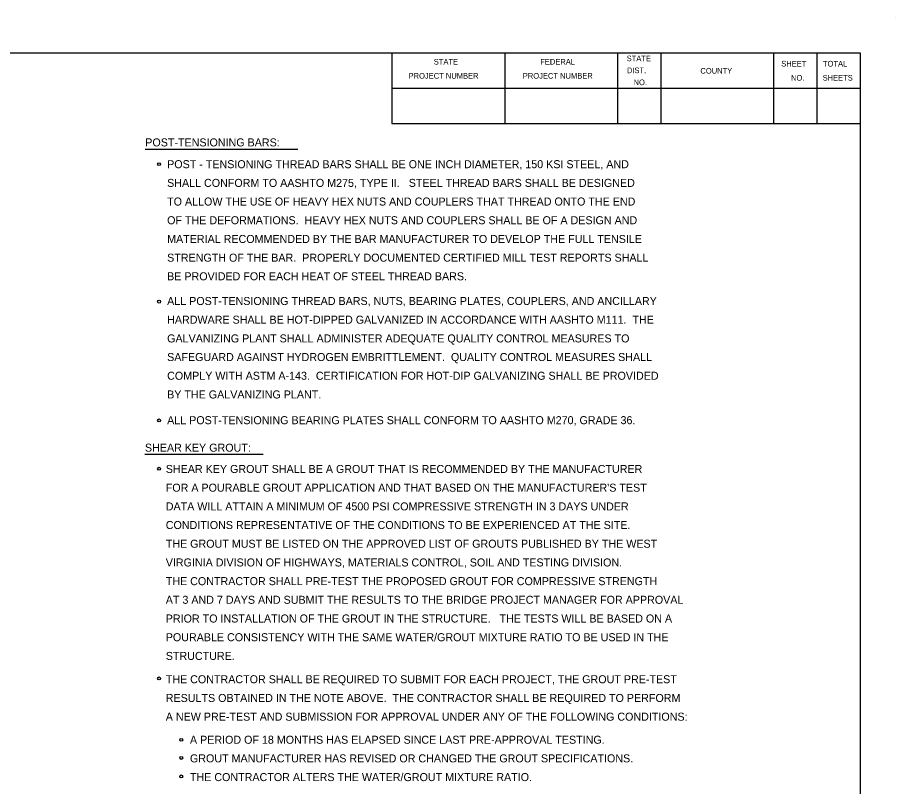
# Model space of a CAD drawing. Extents: x 762.3 to 790.4, y -1231.3 to -1213.2.
# Drawn here: x 780.09 to 790.37, y -1222.18 to -1213.19 of the extents above; entities that cross this region are included whole.
import ezdxf

# ---------------------------------------------------------------- set-up
doc = ezdxf.new("R2010")
doc.units = 0
doc.layers.add('Default', color=7, linetype='Continuous')

msp = doc.modelspace()

# ---------------------------------------------------------------- linework, layer by layer
at = {"layer": 'Default'}
for p, q in [((790.367, -1213.186), (790.367, -1213.186)), ((763.554, -1213.599), (789.954, -1213.599)), ((784.472, -1213.599), (784.472, -1214.424)), ((785.293, -1213.599), (785.293, -1213.599)), ((785.792, -1213.599), (785.792, -1214.424)), ((787.112, -1213.599), (787.112, -1214.424)), ((787.619, -1213.599), (787.619, -1214.424)), ((788.939, -1213.599), (788.939, -1214.424)), ((789.447, -1213.599), (789.447, -1214.424)), ((789.954, -1213.599), (789.954, -1230.924)), ((789.954, -1213.599), (789.954, -1213.599)), ((789.954, -1213.599), (789.954, -1213.599)), ((784.472, -1214.011), (789.954, -1214.011)), ((784.472, -1214.424), (789.954, -1214.424)), ((781.582, -1214.726), (783.369, -1214.726)), ((781.58, -1218.295), (782.963, -1218.295))]:
    msp.add_line(p, q, dxfattribs=at)
for centre in [(781.746, -1214.902), (781.746, -1216.511), (781.746, -1217.901), (781.746, -1218.467), (781.746, -1220.92), (782.005, -1221.639), (782.005, -1221.851), (782.005, -1222.067)]:
    msp.add_circle(centre, 0.0172, dxfattribs=at)

# ---------------------------------------------------------------- texts
for s, height, p in [('STATE', 0.066, (784.962, -1213.736)), ('FEDERAL ', 0.066, (786.208, -1213.736)), ('STATE', 0.066, (787.22, -1213.697)), ('SHEET ', 0.066, (789.03, -1213.759)), ('TOTAL ', 0.066, (789.518, -1213.759)), ('DIST. ', 0.066, (787.223, -1213.837)), ('COUNTY', 0.066, (788.083, -1213.842)), ('PROJECT NUMBER', 0.066, (784.667, -1213.901)), ('PROJECT NUMBER', 0.066, (786.004, -1213.901)), ('NO.', 0.066, (787.301, -1213.977)), ('NO.', 0.066, (789.144, -1213.924)), ('SHEETS', 0.066, (789.514, -1213.924)), ('POST-TENSIONING BARS:', 0.09375, (781.584, -1214.694)), ('POST - TENSIONING THREAD BARS SHALL BE ONE INCH DIAMETER, 150 KSI STEEL, AND', 0.09375, (781.84, -1214.949)), ('SHALL CONFORM TO AASHTO M275, TYPE II.   STEEL THREAD BARS SHALL BE DESIGNED', 0.09375, (781.84, -1215.168)), ('TO ALLOW THE USE OF HEAVY HEX NUTS AND COUPLERS THAT THREAD ONTO THE END', 0.09375, (781.84, -1215.386)), ('OF THE DEFORMATIONS.  HEAVY HEX NUTS AND COUPLERS SHALL BE OF A DESIGN AND', 0.09375, (781.84, -1215.605)), ('MATERIAL RECOMMENDED BY THE BAR MANUFACTURER TO DEVELOP THE FULL TENSILE', 0.09375, (781.84, -1215.824)), ('STRENGTH OF THE BAR.  PROPERLY DOCUMENTED CERTIFIED MILL TEST REPORTS SHALL', 0.09375, (781.84, -1216.043)), ('BE PROVIDED FOR EACH HEAT OF STEEL THREAD BARS.', 0.09375, (781.84, -1216.261)), ('ALL POST-TENSIONING THREAD BARS, NUTS, BEARING PLATES, COUPLERS, AND ANCILLARY', 0.09375, (781.84, -1216.55)), ('HARDWARE SHALL BE HOT-DIPPED GALVANIZED IN ACCORDANCE WITH AASHTO M111.  THE', 0.09375, (781.84, -1216.769)), ('GALVANIZING PLANT SHALL ADMINISTER ADEQUATE QUALITY CONTROL MEASURES TO ', 0.09375, (781.84, -1216.988)), ('SAFEGUARD AGAINST HYDROGEN EMBRITTLEMENT.  QUALITY CONTROL MEASURES SHALL ', 0.09375, (781.84, -1217.206)), ('COMPLY WITH ASTM A-143.  CERTIFICATION FOR HOT-DIP GALVANIZING SHALL BE PROVIDED', 0.09375, (781.84, -1217.425)), ('BY THE GALVANIZING PLANT.', 0.09375, (781.84, -1217.644)), ('ALL POST-TENSIONING BEARING PLATES SHALL CONFORM TO AASHTO M270, GRADE 36.', 0.09375, (781.84, -1217.945)), ('SHEAR KEY GROUT:', 0.09375, (781.58, -1218.267)), ('SHEAR KEY GROUT SHALL BE A GROUT THAT IS RECOMMENDED BY THE MANUFACTURER', 0.09375, (781.824, -1218.516)), ("FOR A POURABLE GROUT APPLICATION AND THAT BASED ON THE MANUFACTURER'S TEST", 0.09375, (781.824, -1218.735)), ('DATA WILL ATTAIN A MINIMUM OF 4500 PSI COMPRESSIVE STRENGTH IN 3 DAYS UNDER ', 0.09375, (781.824, -1218.954)), ('CONDITIONS REPRESENTATIVE OF THE CONDITIONS TO BE EXPERIENCED AT THE SITE.', 0.09375, (781.824, -1219.172)), ('THE GROUT MUST BE LISTED ON THE APPROVED LIST OF GROUTS PUBLISHED BY THE WEST', 0.09375, (781.824, -1219.391)), ('VIRGINIA DIVISION OF HIGHWAYS, MATERIALS CONTROL, SOIL AND TESTING DIVISION.', 0.09375, (781.824, -1219.61)), ('THE CONTRACTOR SHALL PRE-TEST THE PROPOSED GROUT FOR COMPRESSIVE STRENGTH', 0.09375, (781.824, -1219.829)), ('AT 3 AND 7 DAYS AND SUBMIT THE RESULTS TO THE BRIDGE PROJECT MANAGER FOR APPROVAL', 0.09375, (781.824, -1220.047)), ('PRIOR TO INSTALLATION OF THE GROUT IN THE STRUCTURE.   THE TESTS WILL BE BASED ON A ', 0.09375, (781.824, -1220.266)), ('POURABLE CONSISTENCY WITH THE SAME WATER/GROUT MIXTURE RATIO TO BE USED IN THE', 0.09375, (781.824, -1220.485)), ('STRUCTURE.   ', 0.09375, (781.824, -1220.704)), ('THE CONTRACTOR SHALL BE REQUIRED TO SUBMIT FOR EACH PROJECT, THE GROUT PRE-TEST', 0.09375, (781.824, -1220.977)), ('RESULTS OBTAINED IN THE NOTE ABOVE.  THE CONTRACTOR SHALL BE REQUIRED TO PERFORM', 0.09375, (781.824, -1221.196)), ('A NEW PRE-TEST AND SUBMISSION FOR APPROVAL UNDER ANY OF THE FOLLOWING CONDITIONS:', 0.09375, (781.824, -1221.415)), ('A PERIOD OF 18 MONTHS HAS ELAPSED SINCE LAST PRE-APPROVAL TESTING.', 0.09375, (782.107, -1221.685)), ('GROUT MANUFACTURER HAS REVISED OR CHANGED THE GROUT SPECIFICATIONS.', 0.09375, (782.107, -1221.903)), ('THE CONTRACTOR ALTERS THE WATER/GROUT MIXTURE RATIO. ', 0.09375, (782.107, -1222.122))]:
    msp.add_text(s, height=height, dxfattribs=at).set_placement(p)

doc.saveas('drawing.dxf')
